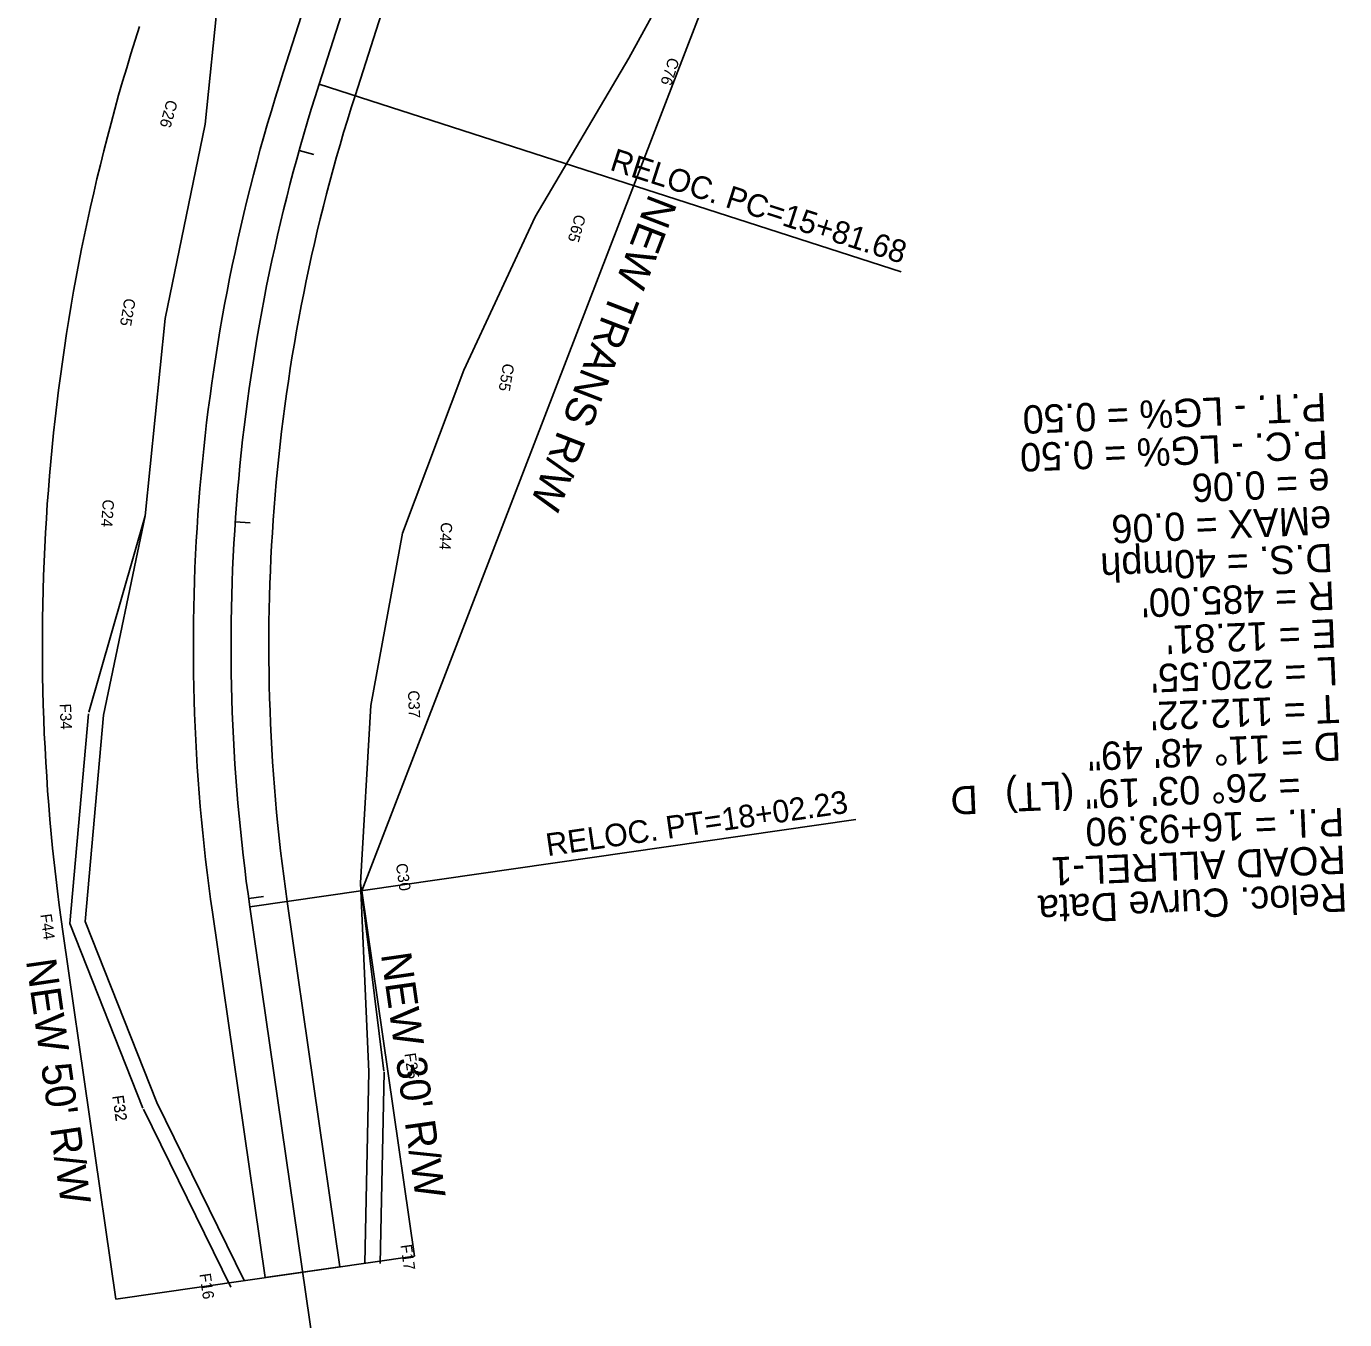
# Model space of a CAD drawing. Extents: x 1475170 to 1480100, y 1103245 to 1119475.
# Drawn here: x 1477142.1 to 1477491.5, y 1110497.3 to 1110839.8 of the extents above; entities that cross this region are included whole.
import ezdxf

# ---------------------------------------------------------------- set-up
doc = ezdxf.new("R2010")
doc.units = 0
for name, color, linetype in [('RD_HC_CL_Rel', 7, 'Continuous'), ('RD_HC_Data_Rel', 7, 'Continuous'), ('RD_HC_Data_Tic_Rel', 7, 'Continuous'), ('RD_PD_CstnLmt', 7, 'Continuous'), ('RD_PD_CstnLmt_TX', 7, 'Continuous'), ('RD_PD_DR_ErosCtrl', 7, 'Continuous'), ('RD_PD_Final_TrvlWay', 7, 'Continuous'), ('RD_PD_RW', 7, 'Continuous'), ('RD_PD_RW_TX', 7, 'Continuous')]:
    doc.layers.add(name, color=color, linetype=linetype)

msp = doc.modelspace()

# ---------------------------------------------------------------- linework, layer by layer
at = {"layer": 'RD_HC_CL_Rel'}
for p, q in [((1477378.79, 1111318.79), (1477219.71, 1110824.5)), ((1477201.37, 1110606.61), (1477249.45, 1110273.62))]:
    msp.add_line(p, q, dxfattribs=at)
msp.add_arc((1477681.39, 1110675.91), 485, 162.16, 188.2153, dxfattribs=at)
at = {"layer": 'RD_HC_Data_Rel'}
for p, q in [((1477219.71, 1110824.5), (1477373.97, 1110774.85)), ((1477201.37, 1110606.61), (1477361.95, 1110629.79))]:
    msp.add_line(p, q, dxfattribs=at)
at = {"layer": 'RD_HC_Data_Tic_Rel'}
for p, q in [((1477214.43, 1110806.96), (1477218.28, 1110805.88)), ((1477197.49, 1110708.58), (1477201.48, 1110708.31)), ((1477201.05, 1110608.82), (1477205.02, 1110609.38)), ((1477215.34, 1110509.85), (1477219.3, 1110510.42))]:
    msp.add_line(p, q, dxfattribs=at)
at = {"layer": 'RD_PD_CstnLmt'}
for p, q in [((1477326.29, 1110876), (1477301.75, 1110831.37)), ((1477194.83, 1110865.79), (1477189.48, 1110813.96)), ((1477301.75, 1110831.37), (1477276.94, 1110789.41)), ((1477189.48, 1110813.96), (1477178.89, 1110762.43)), ((1477276.94, 1110789.41), (1477258.04, 1110748.8)), ((1477178.89, 1110762.43), (1477173.64, 1110710.19)), ((1477258.04, 1110748.8), (1477241.82, 1110705.59)), ((1477173.64, 1110710.19), (1477162.6, 1110657.39)), ((1477241.82, 1110705.59), (1477233.39, 1110659.92)), ((1477162.6, 1110657.39), (1477157.69, 1110602.77)), ((1477233.39, 1110659.92), (1477230.65, 1110612.96)), ((1477230.65, 1110612.96), (1477232.92, 1110562.9)), ((1477157.69, 1110602.77), (1477176.73, 1110554.79)), ((1477232.92, 1110562.9), (1477231.86, 1110512.23)), ((1477176.73, 1110554.79), (1477199.88, 1110507.62))]:
    msp.add_line(p, q, dxfattribs=at)
at = {"layer": 'RD_PD_DR_ErosCtrl'}
for p, q in [((1477173.64, 1110710.19), (1477158.68, 1110658.21)), ((1477158.61, 1110657.75), (1477153.62, 1110602.17)), ((1477230.65, 1110612.96), (1477236.91, 1110563.08)), ((1477153.62, 1110602.17), (1477173.01, 1110553.32)), ((1477236.92, 1110562.82), (1477235.86, 1110512.15)), ((1477173.14, 1110553.03), (1477196.29, 1110505.85))]:
    msp.add_line(p, q, dxfattribs=at)
at = {"layer": 'RD_PD_Final_TrvlWay'}
for p, q in [((1477375.04, 1111274.5), (1477229.23, 1110821.43)), ((1477342.05, 1111237.28), (1477210.19, 1110827.56)), ((1477211.27, 1110608.04), (1477225.24, 1110511.28)), ((1477191.47, 1110605.18), (1477205.44, 1110508.42)), ((1477225.24, 1110511.28), (1477205.44, 1110508.42))]:
    msp.add_line(p, q, dxfattribs=at)
for radius in [495, 475]:
    msp.add_arc((1477681.39, 1110675.91), radius, 162.16, 188.2153, dxfattribs=at)
at = {"layer": 'RD_PD_RW'}
for p, q in [((1477231.06, 1110610.9), (1477350.49, 1110920.74)), ((1477231.06, 1110610.9), (1477245.03, 1110514.13)), ((1477151.88, 1110599.47), (1477165.85, 1110502.7)), ((1477245.03, 1110514.13), (1477165.85, 1110502.7))]:
    msp.add_line(p, q, dxfattribs=at)
msp.add_arc((1477681.39, 1110675.91), 535, 162.16, 188.2153, dxfattribs=at)

# ---------------------------------------------------------------- texts
at = {"layer": 'RD_HC_Data_Rel'}
for s, height, rotation, p in [('RELOC. PC=15+81.68', 6, 342.16, (1477296.48, 1110801.89)), ('P.T. - LG% = 0.50', 7.5, 182.4305, (1477486.48, 1110742.78)), ('P.C. - LG% = 0.50', 7.5, 182.4305, (1477486.9, 1110732.79)), ('e = 0.06', 7.5, 182.4305, (1477487.32, 1110722.8)), ('eMAX = 0.06', 7.5, 182.4305, (1477487.75, 1110712.81)), ('D.S. = 40mph', 7.5, 182.4305, (1477488.17, 1110702.82)), ("R = 485.00'", 7.5, 182.3323, (1477488.73, 1110692.83)), ("E = 12.81'", 7.5, 182.3323, (1477489.14, 1110682.84)), ("L = 220.55'", 7.5, 182.3323, (1477489.55, 1110672.85)), ("T = 112.22'", 7.5, 182.3323, (1477489.95, 1110662.86)), ('D = 11%%d 48\' 49"', 7.5, 182.3323, (1477490.36, 1110652.87)), ('    = 26%%d 03\' 19" (LT)', 7.5, 182.3323, (1477490.77, 1110642.88)), ('RELOC. PT=18+02.23', 6, 8.2153, (1477280.26, 1110620.02)), ('D', 7.5, 182.4305, (1477394.13, 1110638.75)), ('P.I. = 16+93.90', 7.5, 182.3323, (1477491.18, 1110632.88)), ('ROAD ALLREL-1', 7.5, 182.3323, (1477491.58, 1110622.89)), ('Reloc. Curve Data', 7.5, 182.3323, (1477491.99, 1110612.9))]:
    msp.add_text(s, height=height, rotation=rotation, dxfattribs=at).set_placement(p)
at = {"layer": 'RD_PD_CstnLmt_TX'}
for s, rotation, p in [('C76', 252.16, (1477312.39, 1110831.79)), ('C26', 254.3243, (1477179.4, 1110820.58)), ('C65', 254.3243, (1477287.56, 1110790.23)), ('C25', 260.2311, (1477168.17, 1110767.98)), ('C55', 260.2311, (1477268.51, 1110750.71)), ('C24', 266.1379, (1477162.42, 1110714.61)), ('C44', 266.1379, (1477252.05, 1110708.56)), ('C37', 272.0446, (1477243.25, 1110663.9)), ('F34', 272.0446, (1477150.98, 1110660.4)), ('C30', 277.9514, (1477240.05, 1110617.96)), ('F44', 277.9514, (1477145.83, 1110604.57)), ('F25', 278.2153, (1477242.32, 1110567.72)), ('F32', 278.2153, (1477164.86, 1110556.51)), ('F32', 278.2153, (1477164.93, 1110556.52)), ('F17', 278.2153, (1477241.27, 1110517.02)), ('F16', 278.2153, (1477188.01, 1110509.36)), ('F16', 278.2153, (1477188.01, 1110509.36))]:
    msp.add_text(s, height=3, rotation=rotation, dxfattribs=at).set_placement(p)
at = {"layer": 'RD_PD_RW_TX'}
for s, rotation, p in [('NEW TRANS R/W', 248.92, (1477307.23, 1110795.72)), ("NEW 30' R/W", 278.0931, (1477236.09, 1110594.05)), ("NEW 50' R/W", 278.1834, (1477142.02, 1110592.38))]:
    msp.add_text(s, height=8, rotation=rotation, dxfattribs=at).set_placement(p)

doc.saveas('drawing.dxf')
